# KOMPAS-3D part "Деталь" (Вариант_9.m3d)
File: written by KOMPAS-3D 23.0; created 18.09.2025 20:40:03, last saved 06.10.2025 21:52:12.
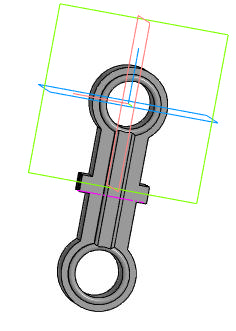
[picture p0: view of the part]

Document properties: Автор: ssafo; Полное имя файла: C:\Users\ssafo\OneDrive\Desktop\ЦД_Грант\Решенные варианты\Вариант_9.m3d

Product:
- Part/product: Деталь
    Масса: 0.120033
    Форматы листов документа: A4

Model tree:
1. Эскиз:1
2. Элемент выдавливания:1
     Расстояние 1 = 8; Расстояние 2 = 8
3. Эскиз:2  (with: Элемент выдавливания:1)
4. Элемент выдавливания:2
     Расстояние 1 = 2
5. Эскиз:3  (with: Элемент выдавливания:2, Элемент выдавливания:1)
6. Элемент выдавливания:3
     Расстояние 2 = 18
7. Зеркальный массив:1
8. Экземпляр ( 1 )
9. Экземпляр ( 2 )  (with: Элемент выдавливания:2, Элемент выдавливания:3)
10. Скругление:2  (with: Элемент выдавливания:2)
     Радиус = 1
11. Скругление:3  (with: Элемент выдавливания:2)
     Радиус = 1
12. Эскиз:5  (with: Элемент выдавливания:1)
13. Элемент выдавливания:6
     Расстояние 2 = 20.9821
14. Фаска:2  (with: Элемент выдавливания:6)
     Угол = 15; Длина 1 = 1; Длина 2 = 0.267949
15. Фаска:3  (with: Элемент выдавливания:6)
     Угол = 15; Длина 1 = 1; Длина 2 = 0.267949
16. Эскиз:6  (with: Элемент выдавливания:1)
